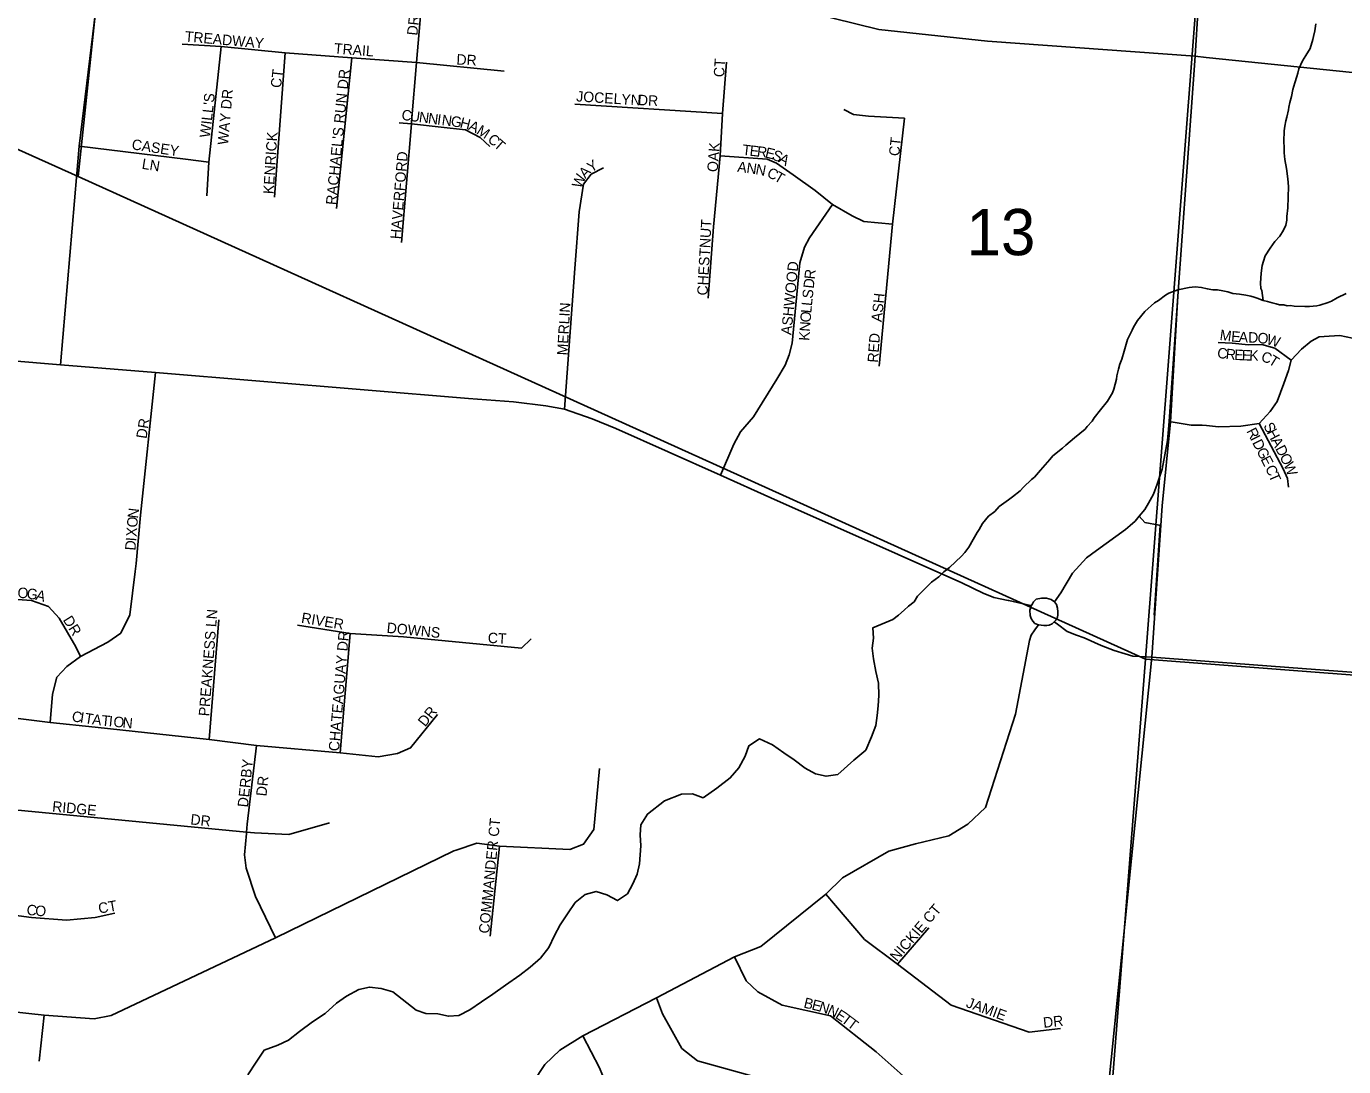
# Model space of a CAD drawing. Extents: x 1310247 to 1552180, y 377264 to 706493.
# Drawn here: x 1403845 to 1410137, y 504859 to 509829 of the extents above; entities that cross this region are included whole.
import ezdxf

# ---------------------------------------------------------------- set-up
doc = ezdxf.new("R2010")
doc.units = 0
for name, color, linetype in [('GM_X_County_Road', 7, 'Continuous'), ('GM_X_Minor_River', 7, 'Continuous'), ('GM_X_Section', 7, 'Continuous'), ('GM_X_Section_Text', 7, 'Continuous'), ('GM_X_State_Route', 7, 'Continuous'), ('GM_X_Township', 7, 'Continuous'), ('GM_X_Township_Road', 7, 'Continuous'), ('GM_X_Township_Subdivision', 7, 'Continuous'), ('GM_X_Township_Subdivision_Text', 7, 'Continuous')]:
    doc.layers.add(name, color=color, linetype=linetype)

msp = doc.modelspace()

# ---------------------------------------------------------------- linework, layer by layer
at = {"layer": 'GM_X_County_Road'}
for points in [[(1409298.1, 507885.2), (1409303.7, 507940.7), (1409345.1, 508540.5), (1409426.8, 509685.9), (1409442, 509919.3), (1409466.5, 510237.3), (1409523.8, 510950), (1409570.3, 511512.4)], [(1401305.8, 508440.1), (1401305.8, 508440.1), (1401584.7, 508413.4), (1402164.8, 508354.2), (1403305.7, 508270.7), (1404009.2, 508211.9)], [(1404009.2, 508211.9), (1404461.7, 508175.1), (1405956.6, 508050.6), (1406172, 508035.4), (1406325.8, 508016.7), (1406415.6, 507999.4), (1406547.3, 507953.6), (1406660.3, 507907.6), (1407160, 507684.4), (1407401, 507577.1), (1408313.2, 507170.6), (1408414.4, 507121.5), (1408466.2, 507101.1), (1408534.4, 507086.2), (1408537.8, 507085.5)], [(1408755.6, 507079.9), (1408785.2, 507122.6), (1408841, 507217.1), (1408909.3, 507289.3), (1408956, 507324.2), (1409094.5, 507425.9), (1409117.3, 507444.7), (1409140.8, 507465.8), (1409160.4, 507488.6), (1409187, 507521.5), (1409205.1, 507550.5), (1409228.5, 507593.7), (1409245.9, 507641.5), (1409269.2, 507712.9), (1409294.7, 507851.1), (1409298.1, 507885.2)], [(1408537.8, 507085.5), (1408558.8, 507081.5), (1408641.3, 507061.4)], [(1408754.2, 506983.4), (1408763.8, 506993.4), (1408769.6, 507005.8), (1408771.6, 507017.9), (1408772.2, 507031.5), (1408770.6, 507048.7), (1408765, 507066.6), (1408755.6, 507079.9), (1408739.7, 507091.3), (1408717.1, 507097.9), (1408694.4, 507097.9), (1408668.5, 507091.7), (1408654.7, 507079.9), (1408650.7, 507070.9), (1408644.1, 507060.7)], [(1408641.3, 507061.4), (1408644.1, 507060.7), (1408637.8, 507039.5), (1408640.3, 507014.8), (1408644.7, 506999.8), (1408651.6, 506988.1), (1408662.2, 506976.4), (1408679.6, 506969.1), (1408704.9, 506966.2), (1408718.3, 506966), (1408730.7, 506968.1), (1408745.2, 506974.4), (1408754.2, 506983.4), (1408769.5, 506972.3)], [(1408769.5, 506972.3), (1408816.7, 506938), (1408861.5, 506921.2)], [(1408861.5, 506921.2), (1408897.3, 506907.8), (1408977.9, 506871.8), (1409040.8, 506847.4), (1409093.1, 506831.5), (1409129.4, 506820.4), (1409220, 506815.1), (1409938.6, 506761), (1410365.3, 506728.9), (1410785.2, 506697.3), (1412080.1, 506594.4), (1412114.6, 506591.5), (1412570.9, 506553.7), (1413550.1, 506484), (1414754.7, 506390.5), (1415877.6, 506308.5)]]:
    msp.add_lwpolyline(points, dxfattribs=at)
at = {"layer": 'GM_X_Minor_River'}
for points in [[(1409752.7, 508519.5), (1409746.3, 508566.8), (1409740.7, 508576.2), (1409739.7, 508602.4), (1409743.5, 508650.5), (1409746.8, 508686.5), (1409753.6, 508706.4), (1409762.6, 508732.2), (1409786.1, 508769.5), (1409807.3, 508800.9), (1409832.4, 508826.1), (1409849.6, 508855.6), (1409860.5, 508879.3), (1409865.4, 508903.2), (1409866.1, 508921.3), (1409869.6, 508961.4), (1409873.4, 509063.8), (1409870.7, 509100), (1409864.5, 509150.5), (1409856, 509193), (1409853.2, 509225.3), (1409852.1, 509249.5), (1409851.2, 509279.6), (1409853, 509329.8), (1409855.8, 509351.8), (1409860.8, 509377.8), (1409865.5, 509395.7), (1409872.8, 509429.6), (1409875.3, 509443.5), (1409880.2, 509465.5), (1409887.2, 509493.4), (1409894.5, 509527.3), (1409903.7, 509559.1), (1409912.9, 509588.9), (1409917.5, 509604.8), (1409922.3, 509626.7), (1409939.8, 509664.3), (1409956.8, 509689.8), (1409976.1, 509723.2), (1409989.8, 509766.9), (1409992.3, 509780.9), (1409999.3, 509806.8), (1410004.6, 509840.8)], [(1407983.3, 506995), (1408010.2, 507016.1), (1408037.2, 507039.3), (1408058, 507058.6), (1408084.9, 507079.7), (1408102, 507107.2), (1408133.4, 507138.2), (1408168.8, 507173.1), (1408204, 507199.9), (1408227, 507223.2), (1408253.9, 507244.3), (1408312.2, 507298.4), (1408326.9, 507316), (1408346, 507341.4), (1408367.4, 507376.8), (1408386.7, 507410.2), (1408395.3, 507426), (1408412.4, 507453.5), (1408439.9, 507488.7), (1408470.9, 507511.6), (1408491.8, 507535), (1408535.3, 507567.6), (1408555.9, 507580.9), (1408591.1, 507609.7), (1408607.8, 507627.2), (1408645.4, 507664), (1408659.9, 507675.5), (1408689.3, 507708.6), (1408733.4, 507759.2), (1408748.1, 507776.8), (1408793.7, 507813.3), (1408810.3, 507828.7), (1408851.8, 507863.4), (1408901.6, 507903.8), (1408912.1, 507917.4), (1408935.2, 507942.7), (1408945.8, 507958.4), (1408975.4, 507997.5), (1409009.1, 508038.5), (1409032.7, 508077.8), (1409039.4, 508095.6), (1409051.2, 508143.4), (1409053.8, 508159.4), (1409061, 508191.3), (1409067.9, 508215.2), (1409076.8, 508239), (1409088.3, 508276.7), (1409104.4, 508332.4), (1409110.9, 508346.2), (1409126.2, 508377.8), (1409132.7, 508391.7), (1409152, 508423.1), (1409187.8, 508466), (1409233.6, 508508.5), (1409252.1, 508519.9), (1409285.2, 508544.8), (1409301.6, 508554.3), (1409344.4, 508570.8), (1409399.1, 508580.8), (1409427.3, 508583.8), (1409457.4, 508580.7), (1409485.4, 508575.6), (1409511.3, 508570.6), (1409533.4, 508569.8), (1409559.3, 508564.8), (1409583.3, 508559.9), (1409607.2, 508553), (1409639.2, 508549.8), (1409669.2, 508544.7), (1409693.1, 508539.8), (1409709.1, 508535.2), (1409723, 508530.6), (1409752.7, 508519.5), (1409772.6, 508514.7), (1409794.5, 508507.9), (1409814.4, 508503.1), (1409830.4, 508498.5), (1409850.4, 508497.8), (1409866.4, 508493.2), (1409882.5, 508494.6), (1409900.5, 508491.9), (1409950.7, 508490.1), (1409972.8, 508491.3), (1410009.1, 508494), (1410023.3, 508497.4), (1410062, 508510.1), (1410078.3, 508515.5), (1410105.1, 508532.6), (1410148.1, 508553.1)], [(1407077.7, 506144), (1407143.3, 506190.2), (1407206.9, 506238.4), (1407248.5, 506287.3), (1407278.2, 506342.6), (1407295.8, 506392.3), (1407346.9, 506424.8), (1407408.3, 506396.8), (1407463.4, 506359), (1407512.5, 506325.4), (1407565.5, 506285.7), (1407614.9, 506258.1), (1407664.7, 506246.5), (1407721.2, 506254.8), (1407797.4, 506322.7), (1407855, 506371.2), (1407881, 506434.6), (1407902.6, 506488.1), (1407908.1, 506536.1), (1407913.4, 506582.1), (1407916.9, 506632.2), (1407914.6, 506690.5), (1407902.2, 506747), (1407892, 506807.5), (1407885.4, 506857.9), (1407890.9, 506905.9), (1407888.3, 506956.2), (1407983.3, 506995)], [(1404903.4, 504819.7), (1404943.3, 504880.7), (1404981.1, 504937.7), (1405046.1, 504961.8), (1405096.9, 504986.3), (1405150.3, 505026.9), (1405211.9, 505073.1), (1405273.3, 505113.4), (1405326.9, 505162), (1405374.1, 505196.6), (1405433.2, 505226.9), (1405483.7, 505239.5), (1405539.7, 505231.7), (1405595.4, 505216), (1405662.1, 505163.8), (1405707.2, 505128.2), (1405752.9, 505112.8), (1405811, 505111), (1405860.9, 505099.5), (1405911.2, 505104), (1405964.1, 505130.4), (1406019.5, 505168.9), (1406072.7, 505205.4), (1406134.2, 505247.7), (1406201.8, 505295.8), (1406251.1, 505334.4), (1406300.5, 505377), (1406340.2, 505428), (1406368, 505485.4), (1406395.5, 505536.7), (1406429.2, 505589.9), (1406466.9, 505642.9), (1406514.2, 505681.6), (1406566.8, 505696), (1406618.5, 505680.4), (1406667.9, 505652.8), (1406717, 505685.4), (1406742.5, 505732.8), (1406761.9, 505778.4), (1406773.4, 505828.2), (1406780, 505914.3), (1406777.5, 505966.6), (1406780.9, 506014.6), (1406812.5, 506065.8), (1406892.7, 506129.6), (1406973.9, 506161.3), (1407026.1, 506161.7), (1407077.7, 506144)]]:
    msp.add_lwpolyline(points, dxfattribs=at)
at = {"layer": 'GM_X_Section'}
for points in [[(1399128.9, 513068.6), (1404461.2, 512601.7), (1404092.3, 509111.6), (1403401, 509422.4), (1398704.7, 508684.1)], [(1404461.2, 512601.7), (1409601, 512131.4), (1409190.5, 506806), (1404092.3, 509111.6)], [(1409601, 512131.4), (1414953.7, 511702.6), (1414533.6, 506397), (1409190.5, 506806)], [(1403401, 509422.4), (1404092.3, 509111.6), (1409190.5, 506806), (1408766.1, 501397.1), (1402970.8, 503976.8)], [(1414533.6, 506397), (1414234.1, 502333.5), (1408766.1, 501397.1), (1409190.5, 506806)]]:
    msp.add_lwpolyline(points, close=True, dxfattribs=at)
at = {"layer": 'GM_X_State_Route'}
for points in [[(1402203.7, 510997.5), (1402629, 510933.1), (1403381.5, 510841.9), (1404261.9, 510745.8), (1404851, 510674.6), (1405396.2, 510550.4), (1405846.6, 510403.7), (1406638.8, 510166), (1407367.9, 509949.6), (1407917.5, 509814.2), (1408435.2, 509758.4), (1409426.8, 509685.9), (1409479.3, 509680.4)], [(1409479.3, 509680.4), (1410613.6, 509563.2), (1412222.5, 509467.6), (1413312.6, 509542.6), (1413926.1, 509528.9), (1414437, 509472.1), (1414682.6, 509414.2), (1414995.4, 509319.2), (1415162.2, 509272.9), (1415632.6, 509173.2), (1416062.4, 509116.6)]]:
    msp.add_lwpolyline(points, dxfattribs=at)
at = {"layer": 'GM_X_Township'}
for points in [[(1410116, 518442), (1410088.6, 518108.2), (1410064.7, 517803.3), (1409948.4, 516314.6), (1409874.5, 515368.4), (1409861.4, 515222.7), (1409844.6, 515059.3), (1409782, 514287), (1409740.7, 513801.1), (1409681.2, 513028.9), (1409669.4, 512894.2), (1409621.7, 512132.5), (1409523.8, 510950), (1409466.5, 510237.3), (1409442, 509919.3), (1409426.8, 509685.9), (1409345.1, 508540.5), (1409309.2, 507939.2), (1409269.5, 507539), (1409220, 506815.1), (1408752, 502179.6), (1408158.9, 494897.9)], [(1414754.7, 506390.5), (1413538.4, 506479.9), (1412570.8, 506553.8), (1412114.6, 506591.6), (1412080.1, 506594.4), (1410785.2, 506697.3), (1410365.3, 506728.9), (1409938.7, 506761), (1409220, 506815.1), (1409269.5, 507539), (1409309.2, 507939.2), (1409345.1, 508540.5), (1409426.8, 509685.9), (1409442, 509919.3)], [(1408158.9, 494897.9), (1408752, 502179.6), (1409220, 506815.1), (1409938.7, 506761), (1410365.3, 506728.9), (1410785.2, 506697.3), (1412080.1, 506594.4), (1412114.6, 506591.6), (1412570.8, 506553.8), (1413538.4, 506479.9), (1414754.7, 506390.5), (1415877.6, 506308.5), (1417102.2, 506217.1), (1418070.9, 506124.4), (1418831.7, 506057.7), (1419038.1, 506039.2), (1419868, 505981.9), (1420467.7, 505924.2), (1420708.1, 505905.7), (1421475, 505838), (1421803, 505818.4), (1422757.2, 505730.2), (1423386.7, 505686.1), (1424357.6, 505618.1)]]:
    msp.add_lwpolyline(points, dxfattribs=at)
at = {"layer": 'GM_X_Township_Road'}
for points in [[(1404009.2, 508211.9), (1404098.4, 509256.9), (1404198.7, 510082.5), (1404261.9, 510745.8)], [(1409255.3, 507446.1), (1409187.5, 507459.4), (1409160.4, 507488.6)], [(1409231.1, 507015.7), (1409260.6, 507445), (1409255.3, 507446.1)], [(1406266, 504785.2), (1406321.4, 504868.7), (1406393.1, 504938.4), (1406503.6, 505006.2), (1406855.1, 505187.4), (1407227.4, 505384.5), (1407352.9, 505432.4), (1407663.5, 505683.3), (1407743.1, 505761), (1407964.2, 505888.5), (1408091.6, 505924.3), (1408250.9, 505962.1), (1408342.5, 506017.9), (1408426.2, 506097.6), (1408569.5, 506543.7), (1408636.2, 506894.5), (1408644.2, 506920), (1408661.3, 506946.2), (1408679.6, 506969.1)]]:
    msp.add_lwpolyline(points, dxfattribs=at)
at = {"layer": 'GM_X_Township_Subdivision'}
for points in [[(1405637.5, 508796.4), (1405684.7, 509362.6), (1405685.5, 509372.5), (1405709.2, 509656.3), (1405733.9, 509952.4), (1405750.1, 510146.7), (1405674.1, 510167.9), (1405472.5, 510232.4)], [(1404590.1, 509744.5), (1404775.3, 509732.5), (1405082, 509702.6), (1405400.7, 509677.8), (1405709.2, 509656.3), (1406127.5, 509614.2)], [(1404707.6, 509019.5), (1404717.6, 509180.8), (1404775.3, 509732.5)], [(1405030.2, 509013.5), (1405082, 509702.6)], [(1405327.1, 508959.3), (1405400.7, 509677.8)], [(1407101.8, 508530.9), (1407127.6, 508871.4), (1407159.2, 509211), (1407170.7, 509413.2), (1407189.4, 509657.2)], [(1406465.3, 509457), (1407170.7, 509413.2)], [(1407918.3, 508205.6), (1407982.3, 508884.7), (1408038.9, 509389.9), (1407867.6, 509399.4), (1407795.6, 509408.3), (1407750.3, 509432.3)], [(1405626.6, 509367.3), (1405684.7, 509362.6), (1405826, 509346.9), (1405942.6, 509335.2), (1406013.3, 509298.7), (1406059.2, 509255.1)], [(1404098.4, 509256.9), (1404605, 509194.6)], [(1404605, 509194.6), (1404717.6, 509180.8)], [(1406415.6, 507999.4), (1406465.4, 508671.9), (1406485.5, 508942.3), (1406505.7, 509075.5), (1406543, 509122.8), (1406601.6, 509153.5)], [(1407159.2, 509211), (1407383.8, 509194.7), (1407428.5, 509175), (1407508.1, 509120.3), (1407612.1, 509044.3), (1407695.2, 508978.5), (1407789.1, 508923.9), (1407844.8, 508897), (1407982.3, 508884.7)], [(1407160, 507684.4), (1407223.6, 507833.6), (1407256.9, 507891.4), (1407318.3, 507964.2), (1407428.9, 508142.9), (1407468.8, 508210.5), (1407488.8, 508259.6), (1407502.3, 508315.4), (1407517, 508464.7), (1407538.7, 508698.9), (1407561.4, 508774.5), (1407586.3, 508819), (1407695.2, 508978.5)], [(1409461.1, 507922.9), (1409482.4, 507922.2), (1409539.1, 507916), (1409646.2, 507919.2), (1409733.4, 507931.9), (1409785.5, 507988.3), (1409818.5, 508037.2), (1409850.4, 508123.3), (1409872.7, 508184.9), (1409886.5, 508234.9), (1409935.4, 508287), (1409981.1, 508324.2), (1410019.6, 508346.2), (1410067.8, 508348.3), (1410118.3, 508351.8), (1410178.9, 508339.1)], [(1409537, 508318.9), (1409604.1, 508314.7), (1409682, 508307), (1409746.2, 508309.3), (1409807.8, 508291.2), (1409886.5, 508234.9)], [(1404365.5, 507225.2), (1404370.1, 507262.7), (1404390, 507493.8), (1404461.7, 508175.1)], [(1409303.7, 507940.7), (1409409, 507924.4), (1409461.1, 507922.9)], [(1409872.7, 507626.8), (1409868.4, 507669.3), (1409847.2, 507715.1), (1409733.4, 507931.9)], [(1403959.9, 506503.9), (1403969.9, 506639.3), (1403991.7, 506719), (1404039.5, 506770.8), (1404103.3, 506818.6), (1404234.7, 506886.3), (1404296.4, 506930.1), (1404340.2, 507017.8), (1404365.5, 507225.2)], [(1403200.3, 507026.7), (1403458.1, 507005.8), (1403523.8, 507019.8), (1403616.3, 507065.8), (1403687.1, 507089.5), (1403736.1, 507095.6), (1403870.3, 507085.5), (1403951.9, 507057.6), (1404001.7, 507001.8), (1404081.4, 506864.4), (1404103.3, 506818.6)], [(1404718.5, 506422.2), (1404764.2, 506993.1)], [(1405140.7, 506968), (1405391.5, 506928.1), (1405646.4, 506912.2), (1406210, 506858.4), (1406255.8, 506902.2)], [(1405343.8, 506358.5), (1405391.5, 506928.1)], [(1403611.4, 506545.7), (1403959.9, 506503.9), (1404174.6, 506480.6), (1404718.5, 506422.2), (1404945.4, 506393.6), (1405343.8, 506358.5), (1405525, 506338.6), (1405618.5, 506354.5), (1405680.3, 506382.4), (1405809.7, 506541.7)], [(1404896.1, 505973.5), (1404896.7, 505979.8), (1404899.7, 506017.9), (1404945.4, 506393.6)], [(1405897.7, 505893.9), (1405996.2, 505927.2), (1406104.4, 505912.3), (1406440.9, 505896.4), (1406506.6, 505922.3), (1406556.4, 505992), (1406582.3, 506282.8)], [(1403136.3, 506149.1), (1403621.4, 506101.5), (1404896.7, 505979.8), (1404935.6, 505976.1), (1405098.9, 505968.1), (1405294, 506023.9)], [(1405035.2, 505474.4), (1404939.5, 505671.4), (1404895.7, 505806.8), (1404887.8, 505870.5), (1404896.1, 505973.5)], [(1403060.8, 505185.5), (1403519.4, 505149.2), (1403929.9, 505105.1), (1404170.1, 505087.7), (1404250.1, 505103.7), (1405035.2, 505474.4), (1405887.4, 505890.4), (1405897.7, 505893.9)], [(1406060.6, 505482.1), (1406104.4, 505912.3)], [(1407663.5, 505683.3), (1407848.7, 505466.2), (1408006, 505348.7), (1408262.9, 505153.5), (1408635.2, 505024.1), (1408784.6, 505042)], [(1403569.6, 505611.6), (1403869.7, 505571.3), (1404037.7, 505558.8), (1404173.7, 505571.3), (1404267.9, 505592.6)], [(1408006, 505348.7), (1408155.4, 505522)], [(1407227.4, 505384.5), (1407283.2, 505269), (1407339, 505217.2), (1407454.4, 505153.5), (1407685.4, 505101.7), (1407904.5, 504930.4), (1408047.8, 504803), (1408219.1, 504735.2), (1408418.2, 504659.6), (1408585.4, 504611.8), (1408712.9, 504599.8), (1408780.6, 504564), (1408828.4, 504436.5), (1408808.5, 504217.4), (1408804.5, 503779.2)], [(1407672.5, 503502.6), (1407729.2, 504082), (1407757.1, 504472.3), (1407715.3, 504564), (1407631.7, 504641.6), (1407512.2, 504735.2), (1407394.7, 504791), (1407050.2, 504886.6), (1406976.5, 504946.4), (1406883, 505111.7), (1406855.1, 505187.4)], [(1403929.9, 505105.1), (1403907, 504885.9)], [(1406503.6, 505006.2), (1406582.8, 504853.7), (1406640, 504713.3), (1406689.8, 504633.7), (1406743.6, 504599.8), (1406843.2, 504562), (1406922.8, 504556)]]:
    msp.add_lwpolyline(points, dxfattribs=at)

# ---------------------------------------------------------------- texts
at = {"layer": 'GM_X_Section_Text'}
msp.add_text('13', height=221, rotation=0.00001, dxfattribs=at).set_placement((1408335.6, 508735.6))
at = {"layer": 'GM_X_Township_Subdivision_Text'}
for s, rotation, p in [('DR', 83.98829, (1405712.6, 509783.5)), ('TREADWAY', 354.93644, (1404600.8, 509756.7)), ('TRAIL', 355.5156, (1405313.5, 509699.5)), ('DR', 356.98872, (1405898.5, 509646.7)), ('CT', 86.62901, (1407177.8, 509585)), ('CT', 83.66313, (1405061.4, 509532.7)), ("RACHAEL'S RUN DR", 84.33252, (1405325.4, 508973.8)), ("WILL'S", 83.66087, (1404722.6, 509295.1)), ('WAY DR', 84.89866, (1404808.3, 509260.9)), ('JOCELYN', 356.3089, (1406470.6, 509470.7)), ('DR', 356.98872, (1406765.3, 509453.1)), ('C', 352.59634, (1405635.2, 509382.6)), ('U', 352.60982, (1405674.4, 509377.5)), ('N', 352.59168, (1405718.1, 509371.9)), ('N', 352.60982, (1405761.7, 509366.2)), ('I', 352.59309, (1405805.3, 509360.5)), ('N', 352.59861, (1405827.2, 509357.7)), ('G', 352.59861, (1405870.8, 509352)), ('H', 345.72257, (1405912.9, 509346.7)), ('A', 334.97453, (1405953.2, 509336.6)), ('M', 327.31019, (1405991.5, 509318.9)), ('CASEY', 351.34741, (1404346.2, 509241.8)), ('KENRICK', 86.30714, (1405026.2, 509026.3)), ('C', 319.10764, (1406044.5, 509282.9)), ('T', 318.99271, (1406074.4, 509257)), ('CT', 83.65713, (1408013.8, 509207.1)), ('HAVERFORD', 85.29221, (1405633.4, 508810.9)), ('OAK', 85.91474, (1407146.9, 509131.6)), ('T', 353.34603, (1407262.8, 509215.5)), ('E', 353.33246, (1407297.8, 509211.4)), ('R', 353.34422, (1407332.8, 509207.3)), ('E', 346.50055, (1407370.6, 509203)), ('S', 337.32339, (1407402.8, 509195.4)), ('A', 330.77025, (1407433.9, 509182.5)), ('LN', 351.03269, (1404394.6, 509148.9)), ('A', 45.83456, (1406514.3, 509099.9)), ('Y', 31.17366, (1406542.4, 509129.4)), ('A', 352.6256, (1407239, 509134.5)), ('N', 352.26092, (1407282.5, 509128.9)), ('N', 349.34812, (1407325.4, 509123.1)), ('C', 333.42409, (1407378.1, 509113.1)), ('W', 67.02769, (1406494.7, 509051.3)), ('T', 329.95693, (1407412.8, 509095.7)), ('CHESTNUT', 86.86386, (1407098.6, 508542.2)), ('ASHWOOD', 84.3709, (1407499, 508352.9)), ('R', 83.93181, (1407610.4, 508618.7)), ('D', 83.92291, (1407605.7, 508574.9)), ('L', 84.33561, (1407597.2, 508491.8)), ('S', 84.03388, (1407600.6, 508526.8)), ('ASH', 83.88393, (1407930.2, 508415.1)), ('MERLIN', 86.75998, (1406429.8, 508256.2)), ('O', 85.45963, (1407590.6, 508413.2)), ('L', 84.96635, (1407594.1, 508456.9)), ('N', 86.09578, (1407587.6, 508369.4)), ('K', 86.29278, (1407584.8, 508325.6)), ('RED', 85.91271, (1407912.6, 508221.2)), ('M', 352.26273, (1409542.6, 508331)), ('E', 355.50643, (1409598, 508323.6)), ('A', 357.01484, (1409634.5, 508320.7)), ('D', 358.96242, (1409680.3, 508318.3)), ('O', 353.05392, (1409722.9, 508317.6)), ('W', 342.8571, (1409764.3, 508312.8)), ('C', 352.04506, (1409530.4, 508245.8)), ('R', 353.84789, (1409571.3, 508240.2)), ('E', 356.77205, (1409613.4, 508235.7)), ('E', 357.62357, (1409649.4, 508233.7)), ('K', 358.69227, (1409685.6, 508232.2)), ('C', 342.64018, (1409739, 508230.3)), ('T', 328.01489, (1409773.8, 508219.9)), ('DR', 81.02618, (1404419.1, 507856.8)), ('R', 297.02667, (1409670.9, 507895.3)), ('S', 297.50595, (1409751.9, 507921.2)), ('H', 297.49848, (1409768.2, 507890)), ('I', 297.03902, (1409688.9, 507860)), ('D', 297.03424, (1409698.9, 507840.4)), ('A', 297.50449, (1409788.5, 507851)), ('D', 297.50353, (1409808.8, 507812)), ('G', 297.01954, (1409718.9, 507801.2)), ('E', 296.79719, (1409738.9, 507762)), ('O', 297.50353, (1409829.1, 507772.9)), ('C', 295.4409, (1409760.4, 507719)), ('W', 291.48296, (1409848.8, 507735.2)), ('T', 293.27035, (1409777.2, 507683.7)), ('N', 83.13117, (1404378.3, 507476.6)), ('O', 85.45963, (1404374.9, 507433.2)), ('X', 85.47052, (1404371.4, 507389.4)), ('D', 85.45963, (1404366.2, 507323.6)), ('I', 85.48272, (1404369.7, 507367.5)), ('O', 356.00782, (1403801.9, 507099.2)), ('G', 351.78644, (1403844.8, 507096.2)), ('A', 345.57409, (1403886.9, 507090.2)), ('DR', 302.00478, (1404018.3, 506993.5)), ('PREAKNESS LN', 85.47041, (1404718.2, 506531.6)), ('RIVER', 350.53768, (1405155.9, 506980.2)), ('DOWNS', 354.3828, (1405564.6, 506931.8)), ('CHATEAGUAY DR', 85.19637, (1405338.6, 506364.5)), ('CT', 356.8158, (1406048.1, 506883.5)), ('DR', 51.34463, (1405749.8, 506479.6)), ('C', 351.29631, (1404060.2, 506509.4)), ('I', 351.28874, (1404099.3, 506503.4)), ('T', 351.29227, (1404121.1, 506500.1)), ('A', 353.05113, (1404157.5, 506494.5)), ('T', 354.24189, (1404202.4, 506489.1)), ('I', 354.27295, (1404237.4, 506485.5)), ('O', 354.2875, (1404259.3, 506483.3)), ('N', 354.28614, (1404303.1, 506479)), ('DERBY', 83.92612, (1404903.6, 506096.2)), ('DR', 83.99398, (1404992, 506149)), ('RIDGE', 354.50652, (1403967.3, 506078.3)), ('DR', 353.9883, (1404627.4, 506016.6)), ('COMMANDER CT', 84.44025, (1406055.8, 505493.4)), ('C', 352.8825, (1403844.4, 505585.4)), ('O', 355.93359, (1403886.6, 505580.2)), ('CT', 10.00871, (1404193.5, 505589.8)), ('NICKIE CT', 49.2141, (1408002.8, 505357.8)), ('B', 346.37433, (1407554.7, 505141.8)), ('E', 346.37433, (1407593.2, 505132.5)), ('N', 342.49993, (1407626.5, 505124.4)), ('N', 334.75113, (1407666.8, 505111.9)), ('E', 327.00232, (1407705.1, 505094)), ('JAMIE', 339.77528, (1408330, 505144.9)), ('T', 323.12792, (1407733.9, 505075.3)), ('T', 323.12792, (1407762, 505054.2)), ('DR', 6.34286, (1408704.1, 505044.2))]:
    msp.add_text(s, height=50, rotation=rotation, dxfattribs=at).set_placement(p)

doc.saveas('drawing.dxf')
